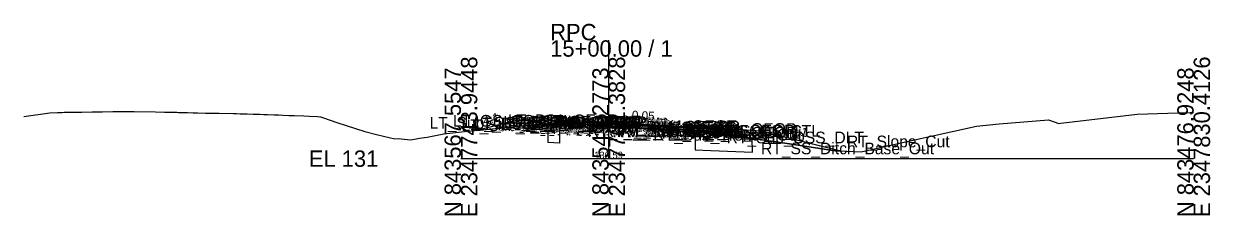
# Model space of a CAD drawing. Extents: x -26 to 203, y -10 to 7538.
# Drawn here: x 0 to 202.8, y 1490.3 to 1523.1 of the extents above; entities that cross this region are included whole.
import ezdxf

# ---------------------------------------------------------------- set-up
doc = ezdxf.new("R2010")
doc.units = 0
for name, color, linetype in [('Default', 7, 'Continuous'), ('Exist CMT Pavement', 7, 'Continuous'), ('Exist Cross Section Cell', 7, 'Continuous'), ('Exist XS Center Line Elevation Label', 7, 'Continuous'), ('Exist XS Ground Line', 7, 'Continuous'), ('Prop CMT Pvmt Course 1', 7, 'Continuous'), ('Prop CMT Pvmt Course 1 Wedge', 7, 'Continuous'), ('Prop CMT Pvmt Course 2', 7, 'Continuous'), ('Prop CMT Pvmt Course 2 Wedge', 7, 'Continuous'), ('Prop CMT Pvmt Course 3', 7, 'Continuous'), ('Prop CMT Pvmt Course 3 Wedge', 7, 'Continuous'), ('Prop CMT Pvmt Surface', 7, 'Continuous'), ('Prop CMT Pvmt Surface Shoulder', 7, 'Continuous'), ('Prop CMT Pvmt Wedge Surface 1', 7, 'Continuous'), ('Prop CMT Pvmt Wedge Surface 2', 7, 'Continuous'), ('Prop CMT Pvmt Wedge Surface 3', 7, 'Continuous'), ('Prop CMT Shld Paved Course 1', 7, 'Continuous'), ('Prop CMT Shld Paved Course 2', 7, 'Continuous'), ('Prop CMT Shld Paved Course 3', 7, 'Continuous'), ('Prop CMT Slope Grass', 7, 'Continuous'), ('Prop CMT Subgrade Earthwork', 7, 'Continuous'), ('Prop Road Sect_ Recs - UC (Outline)', 7, 'Continuous'), ('Prop XS Earthwork Shape', 7, 'Continuous'), ('Prop XS SE Text', 7, 'Continuous'), ('Prop XS Side Slope Text', 7, 'Continuous'), ('Scratch_Level_0', 7, 'Continuous')]:
    doc.layers.add(name, color=color, linetype=linetype)

msp = doc.modelspace()

# ---------------------------------------------------------------- linework, layer by layer
at = {"layer": 'Exist CMT Pavement'}
for q in [(96, 1505.84), (111.49, 1504.73)]:
    msp.add_line((100, 1505.59), q, dxfattribs=at)
at = {"layer": 'Exist Cross Section Cell'}
for p, q in [((100, 1500), (100, 1520.25)), ((74.74, 1500), (100, 1500)), ((100, 1500), (200, 1500))]:
    msp.add_line(p, q, dxfattribs=at)
at = {"layer": 'Exist XS Ground Line'}
msp.add_lwpolyline([(0, 1507.2), (4.49, 1507.85), (5.75, 1507.89), (6.53, 1507.92), (6.9, 1507.93), (8.25, 1507.95), (9.92, 1507.98), (11.69, 1508.01), (13.45, 1508.03), (15.24, 1508.05), (15.91, 1508.05), (16.95, 1508.06), (18.86, 1508.05), (22.5, 1508), (24.05, 1507.97), (25.48, 1507.94), (26.16, 1507.93), (26.48, 1507.92), (27.98, 1507.88), (28.97, 1507.86), (29.71, 1507.84), (31.08, 1507.81), (32.32, 1507.79), (33.43, 1507.77), (35.83, 1507.71), (36.39, 1507.7), (36.98, 1507.68), (38.18, 1507.66), (39.24, 1507.62), (40.36, 1507.59), (41.05, 1507.56), (41.67, 1507.54), (42.8, 1507.51), (43.54, 1507.49), (44.32, 1507.46), (45.33, 1507.41), (46.23, 1507.38), (47.87, 1507.31), (48.81, 1507.27), (50.2, 1507.19), (50.72, 1507.17), (51.23, 1506.97), (53.52, 1506.18), (58.33, 1504.65), (60.56, 1504.06), (63.42, 1503.4), (64, 1503.45), (65.02, 1503.36), (66.15, 1503.21), (67.66, 1503.49), (68.99, 1503.69), (71.81, 1504.23), (75.34, 1504.62), (85.27, 1505.63), (91.59, 1505.92), (92.53, 1505.95), (93.06, 1505.97), (94.85, 1505.9), (95.16, 1505.9), (95.71, 1505.86), (98.58, 1505.69), (100.1, 1505.58), (101.52, 1505.48), (102.21, 1505.43), (104.97, 1505.23), (105.41, 1505.19), (105.85, 1505.16), (108.39, 1504.94), (109.42, 1504.86), (111.05, 1504.75), (111.49, 1504.73), (112.06, 1504.67), (113.07, 1504.59), (114.79, 1504.48), (115.88, 1504.4), (122.71, 1503.75), (130.49, 1502.6), (138.69, 1501.36), (140.73, 1501.3), (143.17, 1501.14), (151.26, 1502.97), (162.87, 1505.55), (166.76, 1505.95), (175.18, 1506.66), (176.96, 1506.02), (177.3, 1506.06), (190.33, 1507.61), (195.57, 1507.76), (199.33, 1507.89), (200, 1507.89)], dxfattribs=at)
at = {"layer": 'Prop CMT Pvmt Course 1'}
for p, q in [((100, 1506.16), (96, 1506.36)), ((96, 1506.36), (96, 1506.11)), ((96, 1506.11), (96, 1506.23)), ((96, 1506.23), (100, 1506.04)), ((96, 1506.11), (96, 1506.11)), ((100, 1505.91), (100, 1506.16)), ((100, 1506.16), (112, 1505.57)), ((100, 1505.91), (100, 1506.16)), ((100, 1506.04), (100, 1505.91)), ((111.49, 1505.47), (100, 1506.04)), ((100, 1506.04), (100, 1505.91)), ((100, 1505.91), (100, 1505.91)), ((100, 1505.91), (100, 1505.91)), ((111.49, 1505.34), (111.49, 1505.47)), ((112, 1505.32), (111.49, 1505.34)), ((112, 1505.57), (112, 1505.32))]:
    msp.add_line(p, q, dxfattribs=at)
at = {"layer": 'Prop CMT Pvmt Course 1 Wedge'}
for q in [(96, 1506.23), (111.49, 1505.47)]:
    msp.add_line((100, 1506.04), q, dxfattribs=at)
at = {"layer": 'Prop CMT Pvmt Course 2'}
for p, q in [((96, 1505.78), (96, 1506.11)), ((96, 1506.11), (96, 1506.11)), ((96, 1506.11), (96, 1505.78)), ((96, 1505.78), (96, 1505.78)), ((111.49, 1505.01), (111.49, 1505.34)), ((111.49, 1505.34), (112, 1505.32)), ((112, 1505.32), (112, 1504.98)), ((112, 1504.98), (111.49, 1505.01))]:
    msp.add_line(p, q, dxfattribs=at)
at = {"layer": 'Prop CMT Pvmt Course 2 Wedge'}
for q in [(96, 1506.11), (111.49, 1505.34)]:
    msp.add_line((100, 1505.91), q, dxfattribs=at)
at = {"layer": 'Prop CMT Pvmt Course 3'}
for p, q in [((96, 1505.78), (96, 1505.78)), ((96, 1505.78), (96, 1505.44)), ((96, 1505.44), (96, 1505.78)), ((96, 1505.44), (96, 1505.44)), ((111.49, 1505.01), (112, 1504.98)), ((111.49, 1504.67), (111.49, 1505.01)), ((112, 1504.65), (111.49, 1504.67)), ((112, 1504.98), (112, 1504.65))]:
    msp.add_line(p, q, dxfattribs=at)
at = {"layer": 'Prop CMT Pvmt Course 3 Wedge'}
for q in [(96, 1505.78), (111.49, 1505.01)]:
    msp.add_line((100, 1505.58), q, dxfattribs=at)
at = {"layer": 'Prop CMT Pvmt Surface'}
for q in [(96, 1506.36), (112, 1505.57)]:
    msp.add_line((100, 1506.16), q, dxfattribs=at)
at = {"layer": 'Prop CMT Pvmt Surface Shoulder'}
for p, q in [((96, 1506.36), (92, 1506.56)), ((112, 1505.57), (122, 1505.07))]:
    msp.add_line(p, q, dxfattribs=at)
at = {"layer": 'Prop CMT Pvmt Wedge Surface 1'}
for p, q in [((96, 1506.11), (96, 1506.36)), ((100, 1506.04), (96, 1506.23)), ((96, 1506.23), (96, 1506.11)), ((96, 1506.11), (96, 1506.11)), ((100, 1506.04), (111.49, 1505.47)), ((111.49, 1505.47), (111.49, 1505.34)), ((111.49, 1505.34), (112, 1505.32)), ((112, 1505.32), (112, 1505.57))]:
    msp.add_line(p, q, dxfattribs=at)
at = {"layer": 'Prop CMT Pvmt Wedge Surface 2'}
for p, q in [((96, 1506.11), (96, 1506.36)), ((100, 1505.91), (96, 1506.11)), ((100, 1505.91), (112, 1505.32)), ((112, 1505.32), (112, 1505.57))]:
    msp.add_line(p, q, dxfattribs=at)
at = {"layer": 'Prop CMT Pvmt Wedge Surface 3'}
for p, q in [((96, 1505.78), (96, 1506.36)), ((100, 1505.58), (96, 1505.78)), ((100, 1505.58), (112, 1504.98)), ((112, 1504.98), (112, 1505.57))]:
    msp.add_line(p, q, dxfattribs=at)
at = {"layer": 'Prop CMT Shld Paved Course 1'}
for p, q in [((92, 1506.56), (91.76, 1506.32)), ((91.76, 1506.32), (96, 1506.11)), ((96, 1506.36), (92, 1506.56)), ((96, 1506.11), (96, 1506.36)), ((112, 1505.57), (122, 1505.07)), ((112, 1505.32), (112, 1505.57)), ((122.26, 1504.81), (112, 1505.32)), ((122, 1505.07), (122.26, 1504.81))]:
    msp.add_line(p, q, dxfattribs=at)
at = {"layer": 'Prop CMT Shld Paved Course 2'}
for p, q in [((91.76, 1506.32), (91.44, 1506)), ((91.44, 1506), (96, 1505.78)), ((96, 1506.11), (91.76, 1506.32)), ((96, 1505.78), (96, 1506.11)), ((112, 1505.32), (122.26, 1504.81)), ((112, 1504.98), (112, 1505.32)), ((122.61, 1504.46), (112, 1504.98)), ((122.26, 1504.81), (122.61, 1504.46))]:
    msp.add_line(p, q, dxfattribs=at)
at = {"layer": 'Prop CMT Shld Paved Course 3'}
for p, q in [((90.94, 1506.03), (90.63, 1505.71)), ((90.63, 1505.71), (96, 1505.44)), ((91.44, 1506), (90.94, 1506.03)), ((96, 1505.78), (91.44, 1506)), ((96, 1505.44), (96, 1505.78)), ((112, 1504.98), (122.61, 1504.46)), ((112, 1504.65), (112, 1504.98)), ((123.46, 1504.08), (112, 1504.65)), ((122.61, 1504.46), (123.11, 1504.43)), ((123.11, 1504.43), (123.46, 1504.08))]:
    msp.add_line(p, q, dxfattribs=at)
at = {"layer": 'Prop CMT Slope Grass'}
for p, q in [((84, 1506.48), (77.45, 1504.84)), ((92, 1506.56), (84, 1506.48)), ((122, 1505.07), (126, 1504.75)), ((126, 1504.75), (139.66, 1501.33))]:
    msp.add_line(p, q, dxfattribs=at)
at = {"layer": 'Prop CMT Subgrade Earthwork'}
for p, q in [((90.63, 1505.71), (82.54, 1506.11)), ((96, 1505.44), (90.63, 1505.71)), ((96, 1505.44), (96, 1505.84)), ((96, 1505.44), (96, 1505.44)), ((111.49, 1504.67), (111.49, 1504.73)), ((111.49, 1504.67), (112, 1504.65)), ((112, 1504.65), (123.46, 1504.08)), ((123.46, 1504.08), (129.97, 1503.76))]:
    msp.add_line(p, q, dxfattribs=at)
at = {"layer": 'Prop Road Sect_ Recs - UC (Outline)'}
for points in [[(91.59, 1505.66), (91.59, 1502.66), (90.63, 1502.71), (89.63, 1502.76), (89.65, 1505.76)], [(122.65, 1503.76), (120.55, 1503.95), (114.79, 1504.48), (114.79, 1501.51), (117.46, 1501.38), (124.59, 1501.12), (124.5, 1503.5)]]:
    msp.add_lwpolyline(points, close=True, dxfattribs=at)
at = {"layer": 'Prop XS Earthwork Shape'}
for points in [[(88.92, 1505.79), (82.54, 1506.11), (77.45, 1504.84), (85.27, 1505.63)], [(96, 1505.44), (96, 1505.84), (95.71, 1505.86), (95.16, 1505.9), (94.85, 1505.9), (93.06, 1505.97), (92.53, 1505.95), (91.59, 1505.92), (88.92, 1505.79), (90.63, 1505.71)], [(100, 1505.59), (96, 1505.84), (98.58, 1505.69)], [(100, 1505.59), (100.1, 1505.58), (101.52, 1505.48), (102.21, 1505.43)], [(104.97, 1505.23), (105.48, 1505.19), (105.41, 1505.19)], [(105.48, 1505.19), (105.85, 1505.16), (108.39, 1504.94), (109.42, 1504.86), (111.05, 1504.75), (111.49, 1504.73)], [(111.49, 1504.67), (111.49, 1504.73), (112.06, 1504.67), (112.92, 1504.6), (112, 1504.65)], [(123.46, 1504.08), (129.97, 1503.76), (139.66, 1501.33), (138.69, 1501.36), (130.49, 1502.6), (122.71, 1503.75), (115.88, 1504.4), (114.79, 1504.48), (113.07, 1504.59), (112.92, 1504.6)]]:
    msp.add_lwpolyline(points, close=True, dxfattribs=at)

# ---------------------------------------------------------------- texts
at = {"layer": 'Default'}
msp.add_text('-', height=0.0001, dxfattribs=at).set_placement((74.74, 1500))
at = {"layer": 'Exist Cross Section Cell'}
for s, p in [('RPC', (90, 1520.25)), ('15+00.00 / 1', (90, 1517.45)), ('EL 131', (48.74, 1498.6))]:
    msp.add_text(s, height=2.8, dxfattribs=at).set_placement(p)
for s, p in [('E 2347743.9448', (77.54, 1490)), ('E 2347761.3828', (102.8, 1490)), ('E 2347830.4126', (202.8, 1490)), ('N 843567.5547', (74.74, 1490)), ('N 843549.2773', (100, 1490)), ('N 843476.9248', (200, 1490))]:
    msp.add_text(s, height=2.8, rotation=90, dxfattribs=at).set_placement(p)
at = {"layer": 'Exist XS Center Line Elevation Label'}
msp.add_text('136.59', height=1.2, dxfattribs=at).set_placement((97.52, 1499.99))
at = {"layer": 'Prop XS SE Text'}
msp.add_text('0.05', height=1.5, rotation=357.1583, dxfattribs=at).set_placement((103.92, 1506.72))
at = {"layer": 'Prop XS Side Slope Text'}
for rotation, p in [(15.5377, (78.77, 1505.72)), (345.9638, (131.09, 1504.34))]:
    msp.add_text('4:1', height=1.5, rotation=rotation, dxfattribs=at).set_placement(p)
at = {"layer": 'Scratch_Level_0'}
for s, p in [('LT_Sub_OSS_DLT', (69.38, 1505.14)), ('LT_GS_OS_CTL', (73.37, 1505.48)), ('LT_PS3_Shelf_Out', (76.93, 1505.03)), ('LT_PS2_OEOP', (82, 1505.32)), ('LT_PS1_OEOP', (82.8, 1505.56)), ('LT_PV2_OEEOP', (85.31, 1505.11)), ('LT_PV1_OEEOP', (85.87, 1505.23)), ('LT_PV2_OEOT', (86.17, 1505.11)), ('LT_PV1_OEOT', (86.74, 1505.36)), ('PV1_PGL', (94.47, 1505.16)), ('LT_Sub_Trench_Out', (74.83, 1504.71)), ('LT_PV_Sub_Tie_Out', (80.95, 1504.84)), ('LT_PS3_OEOP', (81.68, 1505)), ('LT_PV_OEEOP_EG', (83.54, 1504.84)), ('LT_Sub_OEEOP', (85.21, 1504.44)), ('LT_PV3_OEEOP', (85.31, 1504.78)), ('LT_Sub_OEOT', (86.08, 1504.44)), ('LT_PV3_OEOT', (86.17, 1504.78)), ('RT_PV_IEEOP_EG', (88.14, 1504.59)), ('LT_PV_IEEOP_EG', (88.19, 1504.59)), ('RT_PV2_IEEOP', (89.91, 1504.91)), ('RT_PV3_IEEOP', (89.91, 1504.58)), ('LT_PV2_IEEOP', (89.95, 1504.91)), ('LT_PV3_IEEOP', (89.95, 1504.58)), ('RT_PV1_IEEOP', (90.47, 1505.04)), ('LT_PV1_IEEOP', (90.52, 1505.04)), ('PV2_PGL', (93.91, 1504.91)), ('RT_PV_Sub_Tie_Out', (96.39, 1503.73)), ('RT_PV_OEEOP_EG', (98.98, 1503.73)), ('RT_Sub_OEEOP', (100.65, 1503.67)), ('RT_PV2_OEEOP', (100.75, 1504.34)), ('RT_PV3_OEEOP', (100.75, 1504.01)), ('RT_PV1_OEEOP', (101.32, 1504.47)), ('RT_Sub_OEOT', (102.03, 1503.65)), ('RT_PV2_OEOT', (102.13, 1504.32)), ('RT_PV3_OEOT', (102.13, 1503.98)), ('RT_PV1_OEOT', (102.69, 1504.57)), ('RT_Sub_Trench_Out', (107.62, 1503.08)), ('RT_PS3_Shelf_Out', (109.05, 1503.43)), ('RT_PS2_OEOP', (112.45, 1503.81)), ('RT_PS1_OEOP', (112.76, 1504.07)), ('RT_PS3_OEOP', (112.8, 1503.46)), ('RT_GS_OS_CTL', (115.32, 1503.75)), ('RT_Sub_OSS_DLT', (120.15, 1502.62)), ('RT_Slope_Cut', (140.74, 1501.94)), ('RT_SS_Ditch_Base_Out', (126.03, 1500.75))]:
    msp.add_text(s, height=2, dxfattribs=at).set_placement(p)

doc.saveas('drawing.dxf')
